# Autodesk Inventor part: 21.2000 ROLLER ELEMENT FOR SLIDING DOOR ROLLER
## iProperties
Created: 2007-05
Part Number: 21.2000 ROLLER ELEMENT FOR SLIDING DOOR ROLLER
Document SubType Name: Modeling
Designer: Andy Moles
Material: PVC-U
Mass: 6.79827 g
Surface Area: 32.4182 cm^2
Volume: 4.85591 cm^3
Density: 1.4 g/cm^3
Author: Andy Moles
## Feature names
1. Base1
